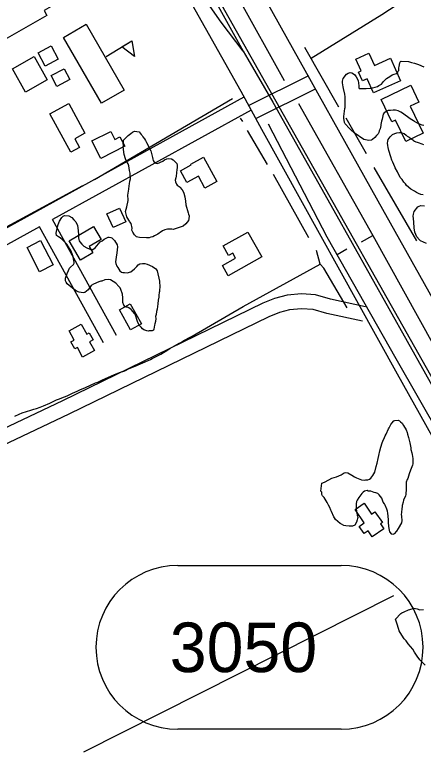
# Model space of a CAD drawing. Extents: x 3187622 to 3225504, y 800805 to 826213.
# Drawn here: x 3199818 to 3200642, y 810315 to 811808 of the extents above; entities that cross this region are included whole.
import ezdxf

# ---------------------------------------------------------------- set-up
doc = ezdxf.new("R2010")
doc.units = 0
for name, color, linetype in [('V-BLDG-OTLN', 7, 'Continuous'), ('V-RAIL-TRAK', 7, 'Continuous'), ('V-ROAD-CNTR', 7, 'Continuous'), ('V-ROAD-IDEN', 7, 'Continuous'), ('V-SITE-VEGE', 7, 'Continuous'), ('V-TOPO-SHOR', 7, 'Continuous')]:
    doc.layers.add(name, color=color, linetype=linetype)

msp = doc.modelspace()

# ---------------------------------------------------------------- linework, layer by layer
at = {"layer": 'V-BLDG-OTLN'}
msp.add_line((3200002.1, 811724.2), (3200053.4, 811755.4), dxfattribs=at)
for points in [[(3199787.3, 811753.2), (3199764.9, 811792.8), (3199752.8, 811786), (3199739, 811810.4), (3199847.2, 811871.5), (3199852.7, 811861.8), (3199865.8, 811869.2), (3199890.9, 811824.9), (3199876.6, 811816.8), (3199882.2, 811806.9)], [(3199961.4, 811789.2), (3200038.2, 811656.3), (3199992.3, 811629.8), (3199915.6, 811762.7)], [(3199878.7, 811704.9), (3199864.7, 811731.5), (3199891.1, 811745.3), (3199905.1, 811718.8)], [(3200053.4, 811755.4), (3200059.1, 811723.8), (3200033.7, 811743.4)], [(3200505.6, 811718.9), (3200532, 811730.9), (3200543.2, 811706), (3200575.4, 811720.6), (3200595.8, 811675.3), (3200541, 811650.5), (3200528.2, 811678.8), (3200519.4, 811674.8), (3200511.3, 811692.6), (3200516.4, 811694.9)], [(3199812.6, 811699.1), (3199856.5, 811723.9), (3199882.9, 811677.3), (3199839, 811652.4)], [(3199890.9, 811685.5), (3199917.3, 811699.4), (3199928.8, 811677.6), (3199902.5, 811663.7)], [(3200641.3, 811569.3), (3200606.2, 811552.6), (3200585.7, 811595.9), (3200578.1, 811592.3), (3200556.6, 811637.7), (3200616.3, 811666), (3200632.5, 811631.9), (3200615.5, 811623.8)], [(3199888.4, 811608.5), (3199926.3, 811629.1), (3199958.7, 811569.2), (3199938.5, 811558.3), (3199948.1, 811540.5), (3199930.4, 811530.9)], [(3200011.2, 811573), (3200019.2, 811557), (3200029.6, 811562.2), (3200039.3, 811543), (3199990.8, 811518.6), (3199973.1, 811553.8)], [(3200198.3, 811520.9), (3200225, 811471.7), (3200201, 811458.7), (3200188, 811482.5), (3200164.5, 811469.7), (3200151.6, 811493.5), (3200173.6, 811505.5), (3200172.8, 811507)], [(3200003.4, 811406.6), (3200028.7, 811418.4), (3200041.5, 811390.8), (3200016.2, 811379.1)], [(3199927.3, 811352.6), (3199976.1, 811381.5), (3199991.7, 811355.2), (3199967.7, 811340.9), (3199975.1, 811328.4), (3199950.3, 811313.7)], [(3200287.9, 811370), (3200315.9, 811319.8), (3200248, 811281.8), (3200236.3, 811302.7), (3200262.9, 811317.5), (3200257.3, 811327.3), (3200248.6, 811322.5), (3200237.7, 811342)], [(3199867.6, 811290.1), (3199842.3, 811338.7), (3199869.6, 811352.9), (3199894.9, 811304.3)], [(3200051.1, 811173.1), (3200028.6, 811213.5), (3200050.4, 811225.6), (3200072.9, 811185.2)], [(3199954.2, 811118), (3199943.8, 811137.1), (3199938.7, 811134.3), (3199930.8, 811148.8), (3199937.4, 811152.4), (3199927.1, 811171.1), (3199951.6, 811184.5), (3199962.7, 811164.2), (3199967.8, 811167), (3199975.7, 811152.6), (3199968.5, 811148.7), (3199978.1, 811131.1)], [(3200538.9, 810755.5), (3200530.3, 810767.9), (3200522.3, 810762.3), (3200512.4, 810776.6), (3200522.6, 810783.6), (3200504, 810810.5), (3200522.3, 810823.2), (3200537.5, 810801.3), (3200544.1, 810805.9), (3200559.2, 810784.1), (3200555.4, 810781.4), (3200562.2, 810771.6)]]:
    msp.add_lwpolyline(points, close=True, dxfattribs=at)
at = {"layer": 'V-RAIL-TRAK'}
msp.add_line((3200278.5, 811734.7), (3200287.5, 811718.5), dxfattribs=at)
for points in [[(3198855.4, 814257.8), (3198922.6, 814139.8), (3198960.2, 814073.1), (3199071.1, 813878.3), (3199140.7, 813755.6), (3199183.3, 813678.1), (3199279.6, 813506.8), (3199322.6, 813432), (3199377.8, 813333), (3199379.7, 813329.8), (3199419.4, 813260.7), (3199526.1, 813071.7), (3199646.2, 812858.1), (3199796, 812592.9), (3199928.1, 812359.1), (3200053.8, 812135.5), (3200181.4, 811909.9), (3200278.5, 811734.7)], [(3200278.5, 811734.7), (3200233.6, 811793.3), (3200211.8, 811825.2), (3200191.9, 811858.2), (3200167.3, 811900.3), (3200093.7, 812031.1), (3199966.2, 812258.9), (3199852.9, 812461.2), (3199716.3, 812702), (3199597.5, 812912.6), (3199461.2, 813154.2), (3199423.7, 813225.5), (3199403, 813270.5), (3199379.7, 813329.8)], [(3200287.5, 811718.5), (3200338, 811631.9), (3200461, 811413.5), (3200683.3, 811018.6), (3200887.7, 810655.9), (3201126.2, 810234.1), (3201189.4, 810122.2), (3201304.1, 809917.1), (3201508.2, 809555.6), (3201585.6, 809419.3), (3201665.2, 809283.8), (3201742.4, 809161.3), (3201817.1, 809048.2), (3201878.1, 808960.1), (3201947.1, 808865.5), (3202034, 808751.3), (3202120.7, 808646.1), (3202187.6, 808570.6), (3202242.2, 808510)]]:
    msp.add_lwpolyline(points, dxfattribs=at)
at = {"layer": 'V-ROAD-CNTR'}
for points in [[(3200023.8, 812201.7), (3200373.7, 811581.3), (3200662.6, 811070.6), (3201171.4, 810169.6), (3201333.6, 809880), (3201463.7, 809645.6), (3201566.7, 809463.3), (3201644.3, 809325.2), (3201727.4, 809195.4), (3201812.3, 809064.3), (3201906.6, 808931.5), (3202033.1, 808764.4), (3202168.5, 808594.6)], [(3200152.9, 812143.7), (3200549.7, 811433), (3200992.7, 810644.1), (3201367.7, 809982.1), (3201588.7, 809587.8), (3201681.8, 809423), (3201726.8, 809344.4), (3201777.7, 809260.6), (3201829.7, 809176.2), (3201885.4, 809091.8), (3201930.3, 809029.6), (3201996.2, 808944), (3202074.9, 808840.7), (3202209.1, 808679.1)], [(3200090.8, 811979.4), (3200273.5, 811654.1), (3200315, 811577.3), (3200589.1, 811084.3), (3200776.7, 810748.5), (3200989, 810377.5), (3201127.9, 810126.1), (3201167.4, 810054.5), (3201359.6, 809715.9), (3201495.6, 809473.8), (3201584, 809317.7), (3201622.7, 809249.3), (3201665.7, 809183.7), (3201711.8, 809112), (3201757.4, 809043.9), (3201816.6, 808956), (3201868.7, 808887.1), (3201917.3, 808818.2), (3201959.2, 808762.8), (3202010.1, 808698.6)], [(3200410, 811684.8), (3200289.6, 811625.3)], [(3200423.3, 811657.9), (3200302.9, 811598.5)], [(3200279.6, 811642.4), (3199344.6, 811126.9), (3199329.1, 811118.5)], [(3200294.1, 811616.2), (3199893.4, 811395.2)], [(3200022.8, 811161.2), (3199893.4, 811395.2)], [(3199867.1, 811380.7), (3199358.9, 811100.5), (3199344.5, 811092.8)], [(3199996.5, 811146.7), (3199867.1, 811380.7)], [(3200525.1, 811219.6), (3200454.7, 811234.8), (3200424.5, 811243.6), (3200395.7, 811245.2), (3200367.1, 811242.9), (3200341.7, 811236.3), (3200318.1, 811226.5), (3199913.5, 811030), (3199724.5, 810940.3)], [(3200518.8, 811190.3), (3200447.3, 811205.7), (3200419.3, 811213.9), (3200396.1, 811215.2), (3200372.1, 811213.3), (3200351.3, 811207.8), (3200330.4, 811199.1), (3199926.5, 811003), (3199737.5, 810913.3)]]:
    msp.add_lwpolyline(points, dxfattribs=at)
at = {"layer": 'V-ROAD-IDEN'}
for p, q in [((3200146.2, 810697.7), (3200476.2, 810697.7)), ((3200146.2, 810697.7), (3200146.2, 810697.7)), ((3200146.2, 810697.7), (3200476.2, 810697.7)), ((3200476.2, 810367.7), (3200146.2, 810367.7)), ((3200476.2, 810367.7), (3200146.2, 810367.7))]:
    msp.add_line(p, q, dxfattribs=at)
for centre, start, end in [((3200146.2, 810532.7), 90.0001, 270.0001), ((3200146.2, 810532.7), 90.0001, 270.0001), ((3200476.2, 810532.7), 270.0001, 90.0001), ((3200476.2, 810532.7), 270.0001, 90.0001)]:
    msp.add_arc(centre, 165, start, end, dxfattribs=at)
at = {"layer": 'V-SITE-VEGE'}
for points in [[(3200478.9, 811671.1), (3200478.9, 811674.6), (3200479.8, 811679.9), (3200486.9, 811688.2), (3200490.4, 811690.4), (3200493.9, 811691.7), (3200497.4, 811691.2), (3200503.1, 811687.7), (3200506.6, 811683.3), (3200510.6, 811675.4), (3200511.8, 811664.8), (3200511.8, 811661.7), (3200512.2, 811659.5), (3200514, 811659.5), (3200517.1, 811659.5), (3200526.7, 811659.5), (3200534.2, 811660.3), (3200537.3, 811660.3), (3200539.5, 811660.7), (3200542.1, 811661.6), (3200544.8, 811662), (3200549.6, 811663.8), (3200552.3, 811665.5), (3200557.5, 811668.6), (3200561.5, 811673.4), (3200567.7, 811679.5), (3200570.8, 811681.7), (3200574.3, 811683.9), (3200579.2, 811687.4), (3200582.7, 811688.7), (3200588, 811690), (3200590.2, 811692.1), (3200591.1, 811694.3), (3200592.4, 811696.1), (3200592.4, 811700.9), (3200593.3, 811703.6), (3200594.6, 811711), (3200595.5, 811713.7), (3200597.3, 811715), (3200611.8, 811714)], [(3200611.8, 811714), (3200617.9, 811712.2), (3200623.7, 811710.9), (3200632, 811707.8), (3200642.5, 811703.3)], [(3200642.9, 811585.1), (3200639.4, 811585.6), (3200634.1, 811587.8), (3200628.4, 811590), (3200624, 811592.7), (3200621.8, 811594.4), (3200615.2, 811598.4), (3200599.5, 811609.9), (3200596.4, 811611.7), (3200593.8, 811613.5), (3200591.1, 811614.8), (3200585.4, 811615.7), (3200581, 811615.7), (3200575.8, 811615.3), (3200570.9, 811614.9), (3200567.9, 811614), (3200563, 811610.5), (3200560.8, 811607.5), (3200558.5, 811597.4), (3200557.2, 811593.4), (3200556.8, 811590.3), (3200555.9, 811587.3), (3200555.9, 811585.1), (3200554.5, 811578.5), (3200552.7, 811574.5), (3200551.8, 811571), (3200550.9, 811568.4), (3200547.4, 811564.9), (3200543.9, 811561), (3200539.5, 811556.6), (3200537.3, 811555.3), (3200532, 811554.4), (3200521.9, 811556.7), (3200502.2, 811570.4), (3200496, 811575.7), (3200492.5, 811579.2), (3200484.2, 811588), (3200482.9, 811591.1), (3200482.1, 811595.9), (3200481.2, 811599), (3200481.7, 811603), (3200482.1, 811608.3), (3200483.5, 811619.2), (3200483.9, 811621.4), (3200484.4, 811629.8), (3200484, 811635.1), (3200484, 811643), (3200483.6, 811647.8), (3200480.6, 811659.7), (3200480.2, 811663.2), (3200478.9, 811671.1)], [(3200052.4, 811387), (3200049.8, 811390.5), (3200049, 811392.3), (3200047.6, 811394), (3200045.9, 811397.1), (3200043.7, 811401.1), (3200040.7, 811411.6), (3200043.4, 811420.9), (3200046.5, 811433.6), (3200046.5, 811438), (3200045.7, 811441.5), (3200045.7, 811444.6), (3200046.1, 811448.5), (3200047.9, 811456.9), (3200048, 811463), (3200048.9, 811467.4), (3200049.8, 811472.7), (3200051.1, 811477.5), (3200050.2, 811484.5), (3200050.3, 811488.5), (3200049, 811494.2), (3200048.6, 811498.6), (3200047.3, 811503.9), (3200046, 811507.4), (3200042.9, 811513.1), (3200040.7, 811517.5), (3200038.1, 811526.8), (3200036.4, 811542.2), (3200036.5, 811544.4), (3200036, 811548.8), (3200036.5, 811551), (3200036.9, 811555.4), (3200043.6, 811562.4), (3200046.2, 811564.5), (3200051.5, 811568.5), (3200055, 811571.5), (3200059, 811573.7), (3200068.7, 811571.9), (3200072.6, 811566.6), (3200074.8, 811564.9), (3200076.1, 811562.2), (3200079.1, 811557.8), (3200080.9, 811554.7), (3200083.5, 811550.8), (3200087.4, 811543.3), (3200089.6, 811538.4), (3200092.2, 811533.6), (3200095.2, 811520.4), (3200095.7, 811517.3), (3200097, 811514.7), (3200097.8, 811512.5), (3200100.5, 811510.2), (3200102.2, 811508.9), (3200105.7, 811508.5), (3200115.9, 811512.8), (3200119.4, 811515.4), (3200124.2, 811517.6), (3200126.9, 811518.5), (3200133.9, 811517.6), (3200137, 811515.8), (3200144.4, 811508.3), (3200145.3, 811504.8), (3200145.2, 811499.5), (3200144.3, 811496), (3200143, 811482.8), (3200142.1, 811479.3), (3200141.2, 811474.9), (3200141.6, 811471.4), (3200143.8, 811466.5), (3200145.1, 811464.8), (3200149, 811462.1), (3200150.8, 811460.4), (3200155.1, 811455.1), (3200157.8, 811450.7), (3200158.6, 811448.5), (3200160.8, 811441), (3200162.1, 811432.6), (3200162.9, 811425.2), (3200167.2, 811408.9), (3200168.1, 811406.2), (3200169, 811402.7), (3200168.9, 811396.6), (3200168.1, 811393.1), (3200162.3, 811386.9), (3200157.5, 811382.1), (3200136.8, 811375.2), (3200134.6, 811375.6), (3200125.8, 811375.7), (3200120.1, 811374.4), (3200115.2, 811372.6), (3200110.8, 811369.1), (3200108.6, 811367.8), (3200106.4, 811366.1), (3200099.4, 811362.2), (3200095.8, 811360.4), (3200091.9, 811359.6), (3200088.8, 811358.7), (3200083.5, 811358.3), (3200069, 811358.8), (3200065.5, 811359.7), (3200063.3, 811360.6)], [(3200641.8, 811445.4), (3200636.5, 811445.8), (3200632.1, 811447.6), (3200627.8, 811449.8), (3200623.8, 811452.5), (3200616.4, 811456.9), (3200608, 811464), (3200605.9, 811467.1), (3200602.4, 811470.6), (3200598.9, 811475.9), (3200595.4, 811480.3), (3200589.7, 811491.8), (3200584.9, 811499.3), (3200584.1, 811501.9), (3200580.1, 811510.7), (3200578, 811515.1), (3200576.2, 811522.1), (3200572.3, 811534.5), (3200570.6, 811540.6), (3200570.2, 811544.6), (3200569.3, 811549), (3200570.2, 811553.4), (3200570.7, 811556.4), (3200574.6, 811562.1), (3200576.9, 811563.9), (3200579.5, 811567), (3200584.3, 811569.1), (3200588.3, 811570), (3200593.6, 811570.8), (3200595.8, 811570.8), (3200598.4, 811570.4), (3200602.8, 811568.6), (3200607.2, 811565.5), (3200608.9, 811563.3), (3200612.9, 811561.1), (3200616.4, 811558.9), (3200620.3, 811555.8), (3200622.1, 811554.9), (3200623.8, 811553.6), (3200626.9, 811551.8), (3200629.1, 811551.3), (3200631.7, 811550.5), (3200638.7, 811547.8), (3200642.3, 811546.9)], [(3200648, 811346.9), (3200636.1, 811352.7), (3200633.9, 811354.5), (3200628.7, 811360.2), (3200626.9, 811365), (3200624.8, 811369.9), (3200623.5, 811378.7), (3200622.7, 811389.7), (3200622.3, 811397.6), (3200621.4, 811402), (3200621.9, 811406.4), (3200622.7, 811408.6), (3200623.6, 811411.6), (3200630.7, 811420.8), (3200633.4, 811422.6), (3200636.9, 811423.9), (3200644.3, 811423)], [(3200109.5, 811271.1), (3200109.5, 811267.6), (3200109.9, 811262.4), (3200109.8, 811250.1), (3200109, 811247.9), (3200108.1, 811243), (3200108, 811239.1), (3200106.7, 811232.5), (3200105.8, 811225.5), (3200104.9, 811214.9), (3200103.5, 811210.1), (3200102.6, 811203.9), (3200101.7, 811199.6), (3200102.1, 811195.6), (3200101.2, 811189.9), (3200100.3, 811185.1), (3200099.4, 811182), (3200098.1, 811174.5), (3200097.2, 811171.9), (3200094.6, 811171), (3200091.9, 811170.6), (3200088.8, 811170.6), (3200086.6, 811170.2), (3200084, 811170.6), (3200077.9, 811172.9), (3200075.2, 811175.1), (3200072.2, 811178.2), (3200070, 811181.2), (3200067.8, 811183.9), (3200064.8, 811189.6), (3200061.3, 811202.4), (3200059.6, 811205.5), (3200052.1, 811213.8), (3200047.7, 811217.4), (3200044.7, 811218.7), (3200042.5, 811218.7), (3200040.3, 811219.6), (3200037.7, 811222.7), (3200035.5, 811228), (3200035.5, 811237.6), (3200034.7, 811245.1), (3200031.6, 811254.4), (3200029.9, 811257.4), (3200027.7, 811260.5), (3200021.6, 811266.7), (3200010.6, 811273.8), (3200006.2, 811274.2), (3199999.2, 811273.4), (3199993.1, 811271.2), (3199990.9, 811270.8), (3199986.9, 811269.5), (3199976.3, 811265.2), (3199971.9, 811262.1), (3199965.7, 811253.8), (3199958.7, 811248.1), (3199955.6, 811247.7), (3199947.7, 811248.6), (3199942, 811251.2), (3199933.7, 811256.6), (3199923.2, 811265.8), (3199921, 811268.9), (3199920.1, 811271.6), (3199920.1, 811276.8), (3199923.2, 811286.5), (3199925.9, 811292.6), (3199927.7, 811297), (3199929.9, 811299.2), (3199936.1, 811304.4), (3199937, 811307.1), (3199937.4, 811309.3), (3199936.1, 811315.9), (3199935.3, 811321.1), (3199931.4, 811331.7), (3199922.6, 811345.8), (3199913.9, 811354.6), (3199909.1, 811358.2), (3199905.6, 811360.4), (3199901.6, 811363), (3199901.2, 811367.9), (3199901.7, 811371.4), (3199903.9, 811380.6), (3199904.8, 811385.4), (3199907.9, 811392), (3199912.3, 811399.5), (3199915, 811402.1), (3199918.1, 811403.4), (3199926.4, 811402.9), (3199932.5, 811399.4), (3199936.9, 811395), (3199940.4, 811391), (3199943.9, 811383.5), (3199945.6, 811373), (3199946, 811364.2), (3199946, 811358.4), (3199946.4, 811355.4), (3199947.3, 811352.3), (3199948.6, 811350.1), (3199952.5, 811345.7), (3199956.5, 811341.7), (3199962.6, 811338.2), (3199970.9, 811334.6)], [(3200063.3, 811360.6), (3200061.1, 811362.3), (3200058.9, 811364.5), (3200055.9, 811369.8), (3200053.7, 811374.2), (3200054.2, 811378.2), (3200052.4, 811387)], [(3199970.9, 811334.6), (3199974.9, 811334.6), (3199979.7, 811338.1), (3199989.9, 811350.3), (3199993.9, 811352.5), (3199997.8, 811355.6), (3200005.7, 811359.5), (3200007.9, 811359.9), (3200011, 811359), (3200013.2, 811358.6), (3200018.9, 811353.3), (3200024.1, 811344.5), (3200025, 811340.1), (3200023.6, 811328.2), (3200021.8, 811319.4), (3200020.9, 811310.2), (3200021.3, 811306.7), (3200023.5, 811301), (3200025.3, 811298.8), (3200029.2, 811292.2), (3200032.7, 811289.5), (3200035.3, 811288.2), (3200038.8, 811288.2), (3200044.5, 811287.7), (3200051.6, 811289.9), (3200059.1, 811296), (3200063.5, 811300.8), (3200066.1, 811303.9), (3200069.7, 811306), (3200074.9, 811306.9), (3200077.1, 811306.9), (3200079.8, 811306.4), (3200084.6, 811305.1), (3200095.1, 811300.7), (3200098.2, 811298.9), (3200101.3, 811296.7), (3200103.5, 811294), (3200104.8, 811291.8), (3200109.5, 811271.1)], [(3200530.8, 810847.8), (3200528.6, 810848.7), (3200523.3, 810847.4), (3200520.2, 810845.3), (3200517.6, 810843.1), (3200511.4, 810834.7), (3200508.3, 810829.5), (3200507, 810826.9), (3200506.1, 810822), (3200506.1, 810818.1), (3200506.5, 810811.9), (3200508.2, 810799.2), (3200509, 810797), (3200509.5, 810794.8), (3200509, 810792.6), (3200508.1, 810789.5), (3200507.2, 810785.1), (3200503.7, 810779), (3200498.8, 810776.8), (3200492.3, 810776.8), (3200485.7, 810777.7), (3200481.7, 810778.6), (3200476.5, 810780.9), (3200474.3, 810782.2), (3200464.6, 810790.6), (3200462.4, 810793.7), (3200461.1, 810795.9), (3200456.8, 810806.4), (3200455.5, 810809.1), (3200453.3, 810814.8), (3200450.7, 810819.6), (3200447.6, 810824.5), (3200441.5, 810834.6), (3200438.5, 810838.1), (3200436.7, 810840.8), (3200437.2, 810843.4), (3200436.8, 810845.6), (3200435, 810847.8), (3200436.8, 810863.6), (3200439, 810864.5), (3200443.9, 810866.7), (3200457.1, 810873.7), (3200466.8, 810876.7), (3200476, 810880.6), (3200482.2, 810884.5), (3200484.8, 810885.4), (3200489.2, 810884.5), (3200497.5, 810880.1), (3200502.8, 810876.5), (3200507.2, 810874.3), (3200516.8, 810870.3), (3200523.9, 810869.8), (3200526.1, 810870.3), (3200529.6, 810870.7), (3200533.1, 810872), (3200535.8, 810873.7), (3200540.2, 810879), (3200544.2, 810886), (3200546.8, 810897.4), (3200548.6, 810904), (3200550.4, 810913.2), (3200551.8, 810919.4), (3200554, 810928.6), (3200556.2, 810936.5), (3200558.9, 810944.8), (3200560.3, 810948.3), (3200563.4, 810955.8), (3200564.7, 810959.3), (3200566.5, 810962.8), (3200571.8, 810973.3), (3200572.7, 810975.5), (3200576.2, 810981.7), (3200578.4, 810984.7), (3200582, 810989.1), (3200584.6, 810990.4), (3200590.8, 810990.8), (3200593.4, 810989.5), (3200596, 810987.7), (3200599.1, 810984.6), (3200602.1, 810979.8), (3200606.9, 810971.4), (3200609.1, 810966.1), (3200610, 810962.2), (3200612.1, 810956), (3200613.4, 810950.7), (3200614.3, 810945), (3200616.4, 810934.9), (3200616.4, 810931.4), (3200618.6, 810925.2), (3200619.5, 810921.7), (3200620.3, 810913.4), (3200620.3, 810906.3), (3200620.3, 810902.8), (3200620.2, 810900.2), (3200616.2, 810890.1), (3200613.1, 810882.2), (3200610.5, 810873.4), (3200609.1, 810870.8), (3200607.3, 810866), (3200606.9, 810863.3), (3200606.9, 810856.3)], [(3200606.9, 810856.3), (3200607.3, 810851.9), (3200606.4, 810841.4), (3200605.5, 810837.4), (3200603.2, 810833), (3200601.9, 810829.5), (3200601, 810825.1), (3200599.2, 810818.5), (3200598.3, 810810.2), (3200597.9, 810807.1), (3200597.8, 810804), (3200597, 810801), (3200597.8, 810796.6), (3200598.2, 810788.2), (3200597.8, 810783.4), (3200590.7, 810772.4), (3200587.6, 810767.2), (3200583.2, 810761.5), (3200580.5, 810760.2), (3200578.3, 810761.1), (3200573.9, 810765.5), (3200572.7, 810772.5), (3200572.2, 810777.3), (3200571.4, 810784.4), (3200571.4, 810790.5), (3200570.2, 810803.3), (3200569.3, 810807.2), (3200568, 810811.6), (3200564.5, 810819.6), (3200563.2, 810822.2), (3200560.6, 810825.7), (3200558, 810833.2), (3200552.7, 810840.3), (3200550.1, 810842.9), (3200546.2, 810844.3), (3200542.7, 810845.2), (3200536.1, 810847.4), (3200533.4, 810847.8), (3200530.8, 810847.8)], [(3200645.7, 810496.6), (3200634.8, 810507.6), (3200629.1, 810514.7), (3200626.5, 810519.1), (3200624.3, 810523.1), (3200620.3, 810528.8), (3200611.2, 810539.4), (3200607.2, 810545.6), (3200603.3, 810550), (3200598.1, 810557.5), (3200593.3, 810565.8), (3200589.4, 810577.3), (3200585.9, 810589.6), (3200596.5, 810601), (3200598.7, 810602.3), (3200603.1, 810604.5), (3200611.9, 810608.4), (3200619, 810610.5), (3200622.5, 810611.4), (3200629.5, 810610.1), (3200634.8, 810608.3), (3200642.2, 810609.1)]]:
    msp.add_lwpolyline(points, dxfattribs=at)
at = {"layer": 'V-TOPO-SHOR'}
for p, q in [((3200361.7, 811674.9), (3200145.4, 812063.3)), ((3200558.1, 811807.8), (3200415.5, 811720)), ((3200471.6, 811621.7), (3200402.9, 811742.1)), ((3200256.7, 811638.6), (3199978, 811475.6)), ((3200277.3, 811593.1), (3200272.8, 811599.7)), ((3200526.9, 811527.5), (3200486.3, 811599.8)), ((3200327.4, 811506.4), (3200287, 811575.1)), ((3200629, 811352.5), (3200542.8, 811500.1)), ((3200410.9, 811358.4), (3200339.3, 811486)), ((3200517.1, 811350.6), (3200540.2, 811363.4)), ((3200433.5, 811305.4), (3200426.2, 811332.6)), ((3200467.9, 811324.6), (3200487.6, 811336)), ((3200581.5, 810636.8), (3199956.1, 810321.1))]:
    msp.add_line(p, q, dxfattribs=at)
for points in [[(3201422.1, 811790.6), (3201381, 811838), (3201294.2, 811931.4), (3201254.3, 811990.4), (3201214.7, 812047.7), (3201185.6, 812082.6), (3201159.6, 812116.1), (3201140.5, 812137.2), (3201129.4, 812147.4), (3201115.5, 812149), (3201105.5, 812146.5), (3201071.2, 812128.6), (3200720.1, 811914), (3200558.1, 811807.8)], [(3200389.8, 811629.4), (3200540.2, 811363.4), (3200694.7, 811084.5), (3200882.3, 810751.9), (3201033.8, 810489.8), (3201208.8, 810160.9)], [(3201153.6, 810125.8), (3200968.9, 810437.4), (3200809.5, 810725.8), (3200586.7, 811114.7), (3200447.9, 811360), (3200329.7, 811587.8)], [(3199954.1, 811463.2), (3199541, 811239.8), (3199332.3, 811124.8)], [(3200175.1, 811160.1), (3200278.3, 811220), (3200433.5, 811305.4)], [(3200487.9, 811217.4), (3200440.8, 811297.1), (3200433.5, 811305.4)], [(3199817.3, 810998.9), (3199826.4, 811003), (3199832.5, 811005.3), (3199850, 811011.2), (3199855.7, 811013.1), (3199861, 811014.2), (3199868.6, 811016.9), (3199875.5, 811019.5), (3199888.4, 811025.1), (3199893.3, 811027.8), (3199901.7, 811031.5), (3199907.4, 811034.1), (3199912.7, 811036), (3199923, 811039.8), (3199929.8, 811043.2), (3199934, 811045), (3199943.5, 811049.2), (3199948.5, 811051.8), (3199959.9, 811056.7), (3199970.1, 811061.2), (3199980.4, 811065.7), (3199985, 811067.6), (3199993, 811071.3), (3200000.2, 811075.1), (3200018.4, 811082.6), (3200021.9, 811084.1), (3200028.7, 811086.7), (3200039.3, 811090.5), (3200048.1, 811094.6), (3200060.6, 811099.5), (3200091.1, 811113.4), (3200094.9, 811115.3), (3200105.1, 811120.6), (3200112, 811123.9), (3200121.1, 811129.2), (3200130.6, 811135.2), (3200148.9, 811145.8), (3200152.3, 811147.7), (3200159.9, 811152.2), (3200169.8, 811157.5), (3200175.1, 811160.1)]]:
    msp.add_lwpolyline(points, dxfattribs=at)

# ---------------------------------------------------------------- texts
at = {"layer": 'V-ROAD-IDEN'}
msp.add_text('3050', height=100, rotation=0.0001, dxfattribs=at).set_placement((3200130.1, 810482.7))

doc.saveas('drawing.dxf')
